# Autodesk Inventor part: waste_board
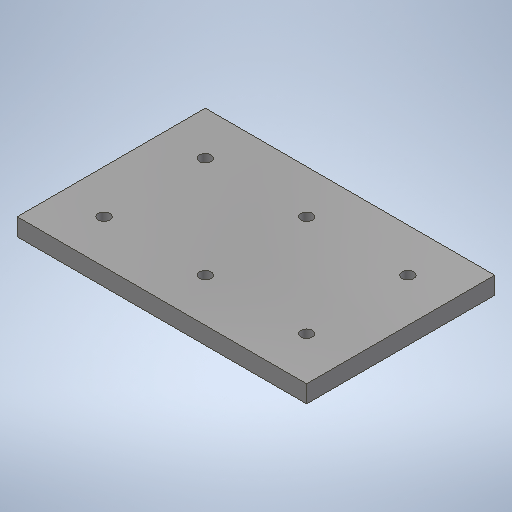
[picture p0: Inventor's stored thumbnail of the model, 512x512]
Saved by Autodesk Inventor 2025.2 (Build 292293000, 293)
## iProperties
Created: 2025-04
Part Number: waste_board
Material: 1.0037 S235JR
Document SubType Name: Modeling
Designer: BennF
Density: 7.85 g/cm^3
Appearance: Stahl
Author: BennF
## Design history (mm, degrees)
sketch "Sketch2"
  geometry: L1 (-100, 65)-(100, 65); L2 (100, 65)-(100, -65); L3 (100, -65)-(-100, -65); L4 (-100, -65)-(-100, 65); 3 further points
  constraints: 8 end point, 2 midpoint, 2 parallel, 1 horizontal, 1 horizontal alignment, 1 perpendicular, 1 vertical alignment
  dimensions: "d0" = 200 distance of L1.start L1.end; "d1" = 130 distance of L3.end L1.start
extrude "Extrusion1" new body sketch "Sketch2" distance "d2" = 12; taper "d3" = 0 deg
sketch "Sketch3"
  geometry: L1 (-70, 35)-(70, 35); L2 (70, 35)-(70, -35); L3 (70, -35)-(-70, -35); L4 (-70, -35)-(-70, 35); L5 (100, 65)-(-100, 65) reference; L6 (-100, 65)-(-100, -65) reference; 7 further points
  constraints: 8 end point, 5 horizontal alignment, 4 vertical alignment, 2 midpoint, 2 parallel, 1 coincident, 1 horizontal, 1 perpendicular
  dimensions: "d11" = 30 distance between parallel lines of L5 L1; "d12" = 30 distance between parallel lines of L6 L4 (= d11)
hole "Hole1" sketch "Sketch3" at (0, 35), (70, 35), (-70, 35), (-70, -35), (0, -35), (70, -35) diameter "d4" = 4.5; stored, may be unused: countersink angle "d8" = 90 deg, drill point angle "d10" = 118 deg; dims "d5" = 4, "d6" = 8, "d7" = 7, "d9" = 8
body "Solid1"
